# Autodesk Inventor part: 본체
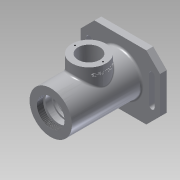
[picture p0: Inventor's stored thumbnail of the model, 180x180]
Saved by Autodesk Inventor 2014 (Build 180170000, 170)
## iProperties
Created: 2017-10
Part Number: 본체
Material: 알루미늄 6061
Document SubType Name: Modeling
Designer: NET
Density: 2.71 g/cm^3
Appearance: 알루미늄 - 평지
Mass: 740.83 g
Surface Area: 654.512 cm^2
Volume: 273.369 cm^3
Author: NET
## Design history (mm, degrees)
sketch "스케치6"
  geometry: L1 (0, 0)-(0, 115); L2 (-21, 0)-(-21, 9); L3 (-21, 9)-(-24, 9); L4 (-24, 9)-(-24, 12); L5 (-24, 12)-(-20, 12); L6 (-20, 12)-(-20, 21); L7 (-20, 21)-(-17.5, 21); L8 (-17.5, 21)-(-17.5, 24.25); L9 (-17.5, 24.25)-(-18.5, 24.25); L10 (-18.5, 24.25)-(-18.5, 26); L11 (-18.5, 26)-(-17.5, 26); L12 (-17.5, 26)-(-17.5, 37); L13 (-17.5, 37)-(-26, 37); L14 (-26, 37)-(-26, 75); L15 (-26, 75)-(-17.5, 75); L16 (-17.5, 75)-(-17.5, 86); L17 (-17.5, 86)-(-16.5, 86); L18 (-16.5, 86)-(-16.5, 91); L19 (-16.5, 91)-(-10, 91); L20 (-10, 91)-(-10, 93.7); L21 (-10, 93.7)-(-12.5, 93.7); L22 (-31, 115)-(-31, 0); L23 (-31, 0)-(-21, 0); L24 (-12.5, 93.7)-(-12.5, 100.3); L25 (-12.5, 100.3)-(-12.904, 101); L26 (-12.904, 101)-(-16, 101); L27 (-16, 101)-(-16, 115); L28 (-16, 115)-(-31, 115)
  constraints: 56 end point, 21 parallel, 5 perpendicular, 2 point on line, 1 collinear, 1 vertical
  dimensions: "d12" = 115 distance of L1.start L1.end; "d25" = 42 diameter of L2 L1; "d27" = 62 diameter of L22 L1; "d28" = 48 diameter of L4 L1; "d29" = 12 distance between parallel lines of L23 L5; "d30" = 3 distance between parallel lines of L5 L3; "d31" = 40 diameter of L6 L1; "d32" = 35 diameter of L8 L1; "d33" = 21 distance between parallel lines of L23 L7; "d34" = 26 distance between parallel lines of L23 L11; "d35" = 1.75 distance between parallel lines of L9 L11; "d36" = 37 diameter of L10 L1; "d37" = 11 distance between parallel lines of L13 L11; "d38" = 35 diameter of L12 L1; "d39" = 52 diameter of L14 L1; "d40" = 38 distance between parallel lines of L15 L13; "d41" = 11 distance between parallel lines of L15 L17; "d42" = 33 diameter of L18 L1; "d43" = 20 diameter of L20 L1; "d46" = 2.7 distance between parallel lines of L19 L21; "d48" = 25 diameter of L24 L1; "d49" = 0.7 vertical distance of L25.end L24.end; "d50" = 30 deg angle of L24 L25; "d51" = 7.3 distance between parallel lines of L26 L21; "d52" = 5 distance between parallel lines of L17 L19; "d57" = 32 diameter of L27 L1
revolve "회전1" sketch "스케치6" stored, may be unused: angle "d58" = 90 deg
sketch "스케치7"
  geometry: C1 r 21 at (0, 0) reference; C2 r 21 at (0, 0) reference; C3 r 31 at (0, 0) reference; C4 r 31 at (0, 0)
  constraints: 1 centre point, 1 coincident
  dimensions: "d59" = 62 diameter of C4
extrude "돌출2" join sketch "스케치7" distance "d60" = 9; taper "d61" = 0 deg
sketch "스케치8"
  geometry: C1 r 24 at (0, 0) reference; C2 r 31 at (0, 0) reference; 1 further point
  constraints: 1 coincident
hole "구멍2" sketch "스케치8" at (0, 0) diameter "d62" = 40.376; stored, may be unused: countersink angle "d66" = 90 deg, drill point angle "d68" = 0 deg; dims "d63" = 6, "d64" = 4, "d65" = 2, "d67" = 9
fillet "모깎기1" dims "d69" = 3
chamfer "모따기1" distance "d70" = 1; stored, may be unused: second distance "d71" = 2, angle "d72" = 45 deg
fillet "모깎기2" dims "d73" = 0.3
fillet "모깎기3" dims "d74" = 3
sketch "스케치10"
  geometry: L1 (0, 0)-(0, 115); L2 (16, 115)-(-16, 115) reference; L3 (31, 115)-(-31, 115) reference; L4 (12.5, 100.3)-(-12.5, 100.3) reference; L5 (-16, 101)-(-22, 115); L6 (-16, 101)-(-16, 115); L7 (16, 101)-(-16, 101) reference
  constraints: 6 end point, 2 perpendicular, 1 midpoint, 1 point on line
  dimensions: "d77" = 32 diameter of L5.start L1; "d78" = 44 diameter of L5.end L1; "d79" = 14 distance from line of L2 L5.start
revolve "회전2" sketch "스케치10" stored, may be unused: angle "d80" = 90 deg
fillet "모깎기4" dims "d81" = 0.3
sketch "스케치11"
  geometry: C1 r 31 at (0, 0) reference; C2 r 35 at (0, 0)
  constraints: 1 centre point, 1 coincident
  dimensions: "d82" = 70 diameter of C2
extrude "돌출3" join sketch "스케치11" distance "d83" = 3; taper "d84" = 0 deg
node "작업 평면1"
sketch "스케치12"
  geometry: L1 (-58, -47)-(58, -47); L2 (58, -47)-(58, 47); L3 (58, 47)-(-58, 47); L4 (-58, 47)-(-58, -47); L5 (-58, -47)-(58, 47); L6 (58, -47)-(-58, 47); L7 (0, -47)-(0, 47); L8 (-58, 0)-(58, 0); L9 (-46, 20)-(-46, -20); L10 (-42, 20)-(-42, -20); L11 (-50, -20)-(-50, 20); L12 (42, 20)-(42, -20); L13 (50, -20)-(50, 20); C1 r 35 at (0, 0) reference; C2 r 22 at (0, 0) reference; C3 r 22 at (0, 0) reference; A1 r 4 centre (-46, 20) between (-42, 20) and (-50, 20); A2 r 4 centre (-46, -20) between (-50, -20) and (-42, -20); A3 r 4 centre (46, 20) between (50, 20) and (42, 20); A4 r 4 centre (46, -20) between (42, -20) and (50, -20); 3 further points
  constraints: 28 end point, 8 midpoint, 8 point on circle, 6 symmetric about line, 4 centre point, 4 parallel, 4 tangent, 1 horizontal, 1 horizontal alignment, 1 perpendicular, 2 other
  dimensions: "d86" = 94 distance between parallel lines of L1 L3; "d87" = 116 distance between parallel lines of L4 L2; "d88" = 46 distance between parallel lines of L7 L9; "d89" = 20 distance of point (-46, 0) L9.end; "d90" = 4 radius of A2
extrude "돌출4" join sketch "스케치12" distance "d91" = 10; taper "d92" = 0 deg
fillet "모깎기5" dims "d93" = 3
node "작업 평면2"
sketch "스케치13"
  geometry: L1 (31, 0)-(-31, 0) reference; C1 r 25 at (0, 56); 1 further point
  constraints: 1 centre point, 1 vertical alignment
  dimensions: "d95" = 50 diameter of C1; "d96" = 56 distance from line of L1 C1.centre
extrude "돌출5" join sketch "스케치13" stored distance "d97" = 10; taper "d98" = 0 deg
sketch "스케치14"
  geometry: C1 r 25 at (0, 0) reference; C2 r 16 at (0, 0); 1 further point
  constraints: 1 centre point, 1 coincident
  dimensions: "d99" = 32 diameter of C2
extrude "돌출6" cut sketch "스케치14" stored distance "d100" = 10; taper "d101" = 0 deg
sketch "스케치15"
  geometry: C1 r 16 at (0, 0) reference; C2 r 25 at (0, 0) reference; A1 r 20.5 centre (0, 0) between (-20.5, 0) and (20.5, 0); 1 further point
  constraints: 2 horizontal alignment, 2 point on circle, 1 centre point, 1 coincident
  dimensions: "d102" = 41 diameter of A1
hole "구멍3" sketch "스케치15" at (-20.5, 0), (20.5, 0) diameter "d103" = 2.459; stored, may be unused: countersink angle "d107" = 82 deg, drill point angle "d109" = 118 deg; dims "d104" = 6, "d105" = 3.023, "d106" = 2, "d108" = 8
fillet "모깎기6" dims "d110" = 3
node "작업 평면3"
sketch "스케치16"
  geometry: L1 (37.909, 42.108)-(74.091, 42.108); L2 (74.091, 42.108)-(74.091, 31.892); L3 (74.091, 31.892)-(37.909, 31.892); L4 (37.909, 31.892)-(37.909, 42.108); L5 (37.909, 37)-(74.091, 37); L6 (56, 42.108)-(56, 31.892); L7 (0, -31)-(0, 31) reference; L8 (31, 47)-(81, 47) reference; 1 further point
  constraints: 4 end point, 4 midpoint, 2 other
  dimensions: "d112" = 56 distance between parallel lines of L7 L6; "d113" = 10 distance between parallel lines of L8 L5
feature "엠보싱1" sketch "스케치16" dims "d12" = 115, "d25" = 42, "d27" = 62, "d28" = 48, "d29" = 12, "d30" = 3, "d31" = 40, "d32" = 35, "d33" = 21, "d34" = 26, "d35" = 1.75, "d36" = 37, "d37" = 11, "d38" = 35, "d39" = 52, "d40" = 38, "d41" = 11, "d42" = 33, "d43" = 20, "d46" = 2.7, "d48" = 25, "d49" = 0.7, "d50" = 30 deg, "d51" = 7.3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
chamfer "모따기2" distance "d116" = 20; stored, may be unused: second distance "d117" = 2, angle "d118" = 45 deg
fillet "모깎기7" dims "d119" = 3
node "솔리드2"
node "투영된 루프2"
node "투영된 루프3"
node "투영된 루프4"
other parameters: "d85" = 112, "d94" = 47
